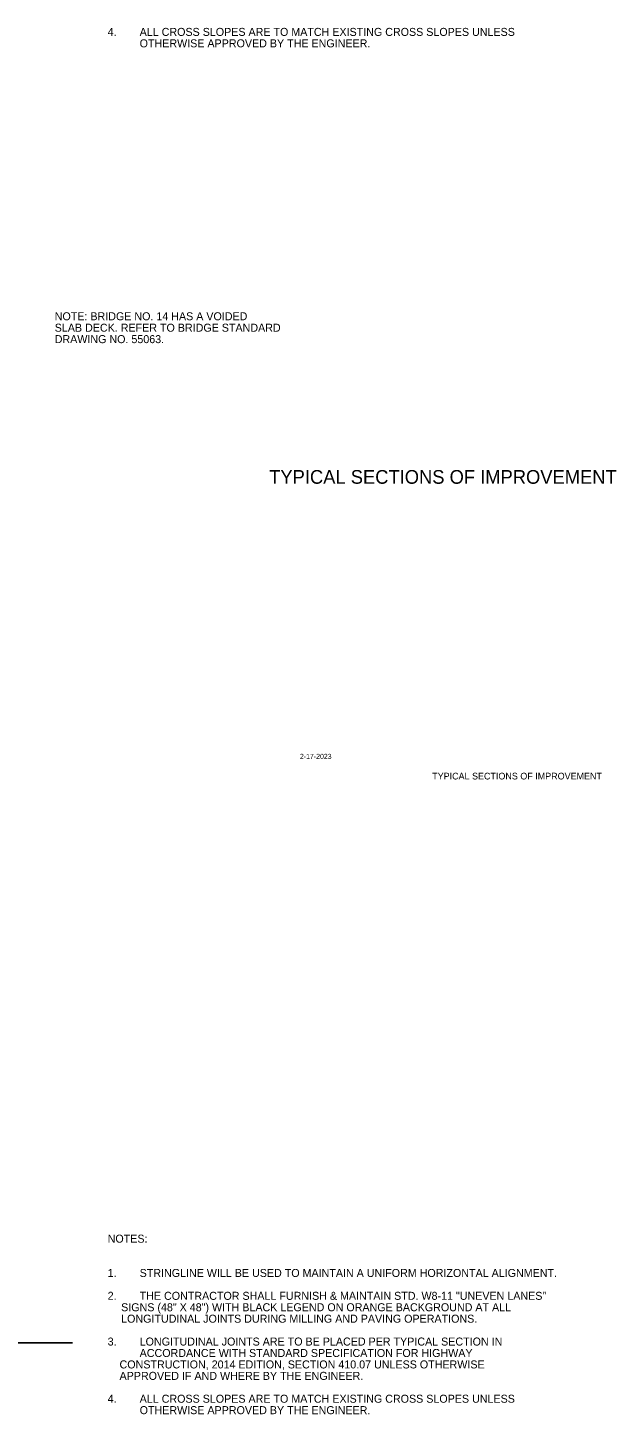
# Model space of a CAD drawing. Extents: x 549600 to 1930787, y -1955432 to 596640.
# Drawn here: x 552031 to 552546, y -1952496 to -1951283 of the extents above; entities that cross this region are included whole.
import ezdxf

# ---------------------------------------------------------------- set-up
doc = ezdxf.new("R2010")
doc.units = 0
for name, color, linetype in [('R_Border', 7, 'Continuous'), ('R_Border Notes', 7, 'Continuous'), ('R_Border Prem', 7, 'Continuous')]:
    doc.layers.add(name, color=color, linetype=linetype)

msp = doc.modelspace()

# ---------------------------------------------------------------- linework, layer by layer
at = {"layer": 'R_Border'}
msp.add_line((551009, -1952433.4), (552070.2, -1952433.4), dxfattribs=at)

# ---------------------------------------------------------------- texts
msp.add_text('TYPICAL SECTIONS OF IMPROVEMENT', height=12, rotation=360, dxfattribs=at).set_placement((552242.3, -1951682.1))
at = {"layer": 'R_Border Notes'}
for s, p in [('4.', (552101, -1951290.4)), ('ALL CROSS SLOPES ARE TO MATCH EXISTING CROSS SLOPES UNLESS ', (552129, -1951290.4)), ('OTHERWISE APPROVED BY THE ENGINEER.', (552129, -1951300.4)), ('NOTE: BRIDGE NO. 14 HAS A VOIDED', (552054.7, -1951539.1)), ('SLAB DECK. REFER TO BRIDGE STANDARD', (552054.7, -1951549.1)), ('DRAWING NO. 55063.', (552054.7, -1951559.1)), ('NOTES: ', (552101, -1952345.8)), ('1.', (552101, -1952375.8)), ('STRINGLINE WILL BE USED TO MAINTAIN A UNIFORM HORIZONTAL ALIGNMENT.', (552129, -1952375.8)), ('2.', (552101, -1952395.8)), ('    SIGNS (48" X 48") WITH BLACK LEGEND ON ORANGE BACKGROUND AT ALL ', (552102.4, -1952405.8)), ('THE CONTRACTOR SHALL FURNISH & MAINTAIN STD. W8-11 "UNEVEN LANES" ', (552129, -1952395.8)), ('    LONGITUDINAL JOINTS DURING MILLING AND PAVING OPERATIONS.', (552102.4, -1952415.8)), ('3.', (552101, -1952435.8)), ('LONGITUDINAL JOINTS ARE TO BE PLACED PER TYPICAL SECTION IN ', (552129, -1952435.8)), ('ACCORDANCE WITH STANDARD SPECIFICATION FOR HIGHWAY', (552129, -1952445.8)), ('    APPROVED IF AND WHERE BY THE ENGINEER.', (552101, -1952465.8)), ('    CONSTRUCTION, 2014 EDITION, SECTION 410.07 UNLESS OTHERWISE', (552101, -1952455.8)), ('4.', (552101, -1952485.8)), ('ALL CROSS SLOPES ARE TO MATCH EXISTING CROSS SLOPES UNLESS ', (552129, -1952485.8)), ('OTHERWISE APPROVED BY THE ENGINEER.', (552129, -1952495.8))]:
    msp.add_text(s, height=7, dxfattribs=at).set_placement(p)
at = {"layer": 'R_Border Prem'}
msp.add_text('2-17-2023', height=4.4, dxfattribs=at).set_placement((552269.2, -1951922.7))
msp.add_text('TYPICAL SECTIONS OF IMPROVEMENT', height=5.862, rotation=360, dxfattribs=at).set_placement((552384.9, -1951940.7))

doc.saveas('drawing.dxf')
